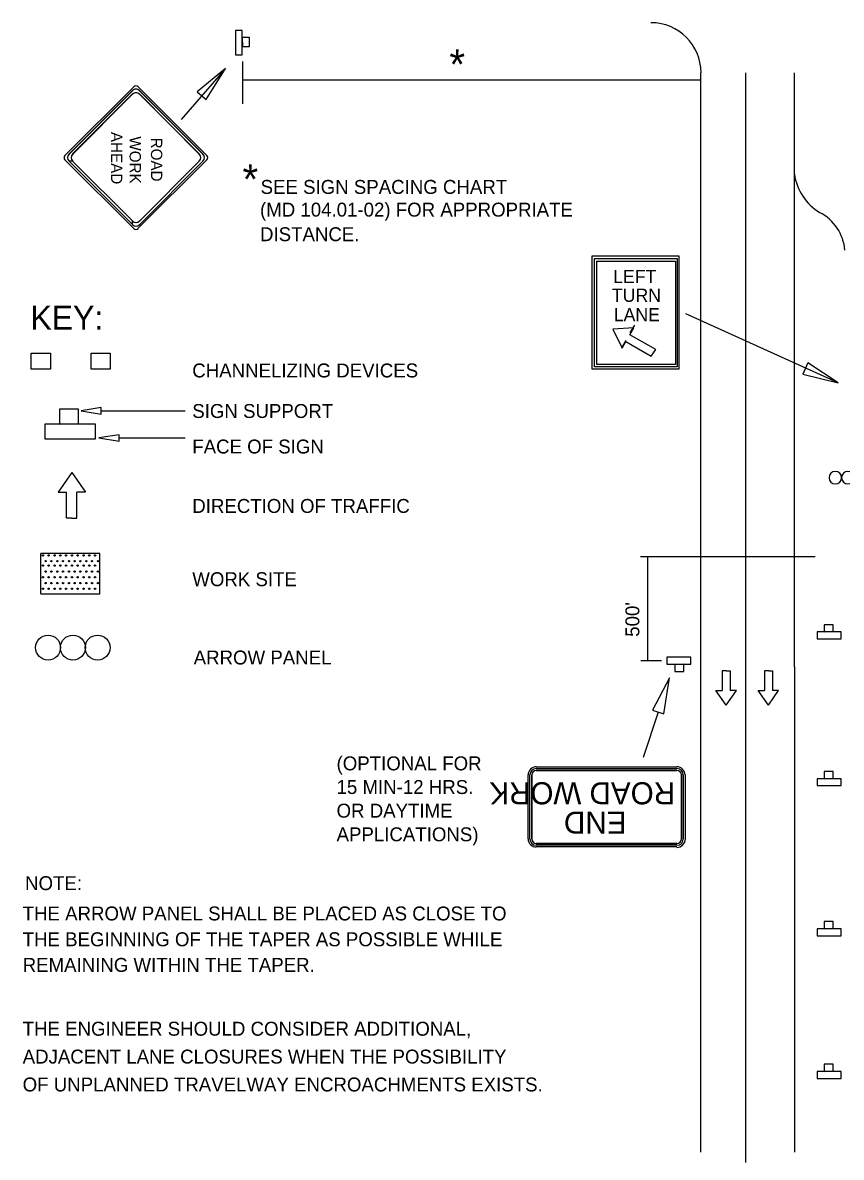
# Model space of a CAD drawing. Extents: x 1531.4 to 1538.6, y 1528.5 to 1539.8.
# Drawn here: x 1531.41 to 1534.932, y 1531.065 to 1535.949 of the extents above; entities that cross this region are included whole.
import ezdxf

# ---------------------------------------------------------------- set-up
doc = ezdxf.new("R2010")
doc.units = 0
for name, color, linetype in [('DETL-DIMS', 7, 'Continuous'), ('DETL-LINE', 7, 'Continuous'), ('DETL-NOTE', 7, 'Continuous'), ('DETL-TITL', 7, 'Continuous'), ('USER-BORD', 7, 'Continuous')]:
    doc.layers.add(name, color=color, linetype=linetype)

# ---------------------------------------------------------------- blocks, each defined once
blk = doc.blocks.new('PANEL')
at = {"layer": 'USER-BORD'}
for centre in [(0.00309, -0.00012), (0.00928, -0.00012), (0.01546, -0.00012)]:
    blk.add_circle(centre, 0.00312, dxfattribs=at)
blk = doc.blocks.new('DIR')
at = {"layer": 'USER-BORD'}
for p, q in [((0, 0.0001), (-0.0034, -0.0048)), ((0, 0.0001), (0.0034, -0.0048)), ((-0.0034, -0.0048), (-0.0013, -0.0048)), ((-0.0013, -0.0113), (-0.0013, -0.0048)), ((0.0034, -0.0048), (0.0013, -0.0048)), ((0.0013, -0.0113), (0.0013, -0.0048)), ((-0.0001, -0.0113), (-0.0013, -0.0113)), ((-0.0001, -0.0113), (0.0001, -0.0113)), ((0.0001, -0.0113), (0.0013, -0.0113))]:
    blk.add_line(p, q, dxfattribs=at)
blk = doc.blocks.new('SIGN')
at = {"layer": 'USER-BORD'}
for points in [[(-0.0013, 0.0018), (0.0011, 0.0019), (0.0011, 0.0037), (-0.0013, 0.0037)], [(-0.0031, 0.0018), (-0.0031, 0), (0.0032, 0), (0.0032, 0.0018)]]:
    blk.add_lwpolyline(points, close=True, dxfattribs=at)
blk = doc.blocks.new('R-BRD0')
at = {"layer": 'USER-BORD'}
for p, q in [((1.415, 2.996), (-1.412, 2.996)), ((-1.5, 2.909), (-1.5, 0.087)), ((-1.45, 0.2), (-1.45, 2.8)), ((-1.375, 2.725), (-1.375, 0.275)), ((-1.3, 2.95), (1.3, 2.95)), ((1.225, 2.875), (-1.225, 2.875)), ((1.375, 0.275), (1.375, 2.725)), ((1.45, 2.8), (1.45, 0.2)), ((1.502, 0.087), (1.502, 2.909)), ((-1.412, 0), (1.415, 0)), ((1.3, 0.05), (-1.3, 0.05)), ((-1.225, 0.125), (1.225, 0.125))]:
    blk.add_line(p, q, dxfattribs=at)
for centre, radius, start, end in [((-1.412, 2.909), 0.0875, 90, 180), ((1.415, 2.909), 0.0875, 0, 90), ((-1.3, 2.8), 0.15, 90, 180), ((-1.225, 2.725), 0.15, 90, 180), ((1.225, 2.725), 0.15, 0, 90), ((1.3, 2.8), 0.15, 0, 90), ((-1.412, 0.087), 0.0875, 180, 270), ((-1.3, 0.2), 0.15, 180, 270), ((-1.225, 0.275), 0.15, 180, 270), ((1.225, 0.275), 0.15, 270, 0), ((1.3, 0.2), 0.15, 270, 0), ((1.415, 0.087), 0.0875, 270, 0)]:
    blk.add_arc(centre, radius, start, end, dxfattribs=at)
blk = doc.blocks.new('W-BRD0')
at = {"layer": 'USER-BORD', "rotation": 45}
blk.add_blockref('R-BRD0', (1.0448, 1.0213), dxfattribs=at)

msp = doc.modelspace()

# ---------------------------------------------------------------- linework, layer by layer
at = {"layer": 'DETL-DIMS'}
for p, q in [((1532.2817, 1535.7516), (1532.091, 1535.5329)), ((1532.3557, 1535.7815), (1532.3557, 1535.5994)), ((1532.3557, 1535.7037), (1534.3286, 1535.7037)), ((1534.9193, 1534.3984), (1534.2634, 1534.6954)), ((1531.7474, 1534.278), (1532.1084, 1534.278)), ((1531.8241, 1534.1617), (1532.1084, 1534.1617)), ((1534.8199, 1533.6499), (1534.0683, 1533.6499)), ((1534.0977, 1533.6499), (1534.0977, 1533.2019)), ((1534.1579, 1533.2019), (1534.0692, 1533.2019)), ((1534.1441, 1532.9814), (1534.0804, 1532.7867))]:
    msp.add_line(p, q, dxfattribs=at)
for points in [[(1532.1605, 1535.6521), (1532.1987, 1535.6184), (1532.2817, 1535.7516)], [(1534.7879, 1534.4845), (1534.7668, 1534.4368), (1534.9193, 1534.3984)], [(1531.7474, 1534.2642), (1531.7474, 1534.2926), (1531.6613, 1534.278)], [(1531.8241, 1534.1471), (1531.8241, 1534.1755), (1531.7379, 1534.1617)], [(1534.12, 1532.99), (1534.1691, 1532.9736), (1534.1924, 1533.1287)]]:
    msp.add_lwpolyline(points, close=True, dxfattribs=at)
at = {"layer": 'DETL-LINE'}
for p, q in [((1534.3285, 1531.0873), (1534.3285, 1535.7337)), ((1534.7307, 1533.1768), (1534.7307, 1535.7337)), ((1531.8815, 1535.6563), (1531.609, 1535.3838)), ((1531.6247, 1535.3838), (1531.8815, 1535.6407)), ((1532.1854, 1535.3838), (1531.913, 1535.6563)), ((1531.913, 1535.6407), (1532.1697, 1535.3838)), ((1534.5198, 1535.6087), (1534.5198, 1531.0427)), ((1531.8815, 1535.0798), (1531.609, 1535.3523)), ((1531.609, 1535.3523), (1531.8815, 1535.0798)), ((1532.1697, 1535.3523), (1531.913, 1535.0955)), ((1531.913, 1535.0798), (1532.1854, 1535.3523)), ((1534.2351, 1534.9444), (1533.8585, 1534.9444)), ((1533.8585, 1534.9444), (1533.8585, 1534.4586)), ((1533.8696, 1534.9342), (1534.2253, 1534.9342)), ((1533.8696, 1534.4682), (1533.8696, 1534.9342)), ((1533.8807, 1534.923), (1534.2185, 1534.923)), ((1533.8807, 1534.4777), (1533.8807, 1534.923)), ((1534.2185, 1534.923), (1534.2185, 1534.4777)), ((1534.2253, 1534.9342), (1534.2253, 1534.4682)), ((1534.2351, 1534.4586), (1534.2351, 1534.9444)), ((1534.0419, 1534.6465), (1534.0228, 1534.6133)), ((1534.0044, 1534.5814), (1533.9858, 1534.5492)), ((1534.2185, 1534.4777), (1533.8807, 1534.4777)), ((1533.8585, 1534.4586), (1534.2351, 1534.4586)), ((1534.2253, 1534.4682), (1533.8696, 1534.4682)), ((1531.741, 1533.6648), (1531.487, 1533.6648)), ((1531.741, 1533.6648), (1531.487, 1533.6648)), ((1531.741, 1533.6648), (1531.487, 1533.6648)), ((1531.741, 1533.6648), (1531.487, 1533.6648)), ((1531.4871, 1533.4908), (1531.4871, 1533.6648)), ((1531.4871, 1533.4909), (1531.4871, 1533.6648)), ((1531.4956, 1533.6559), (1531.4956, 1533.6559)), ((1531.4964, 1533.6559), (1531.4964, 1533.6559)), ((1531.5212, 1533.6559), (1531.5212, 1533.6559)), ((1531.5212, 1533.6559), (1531.5212, 1533.6559)), ((1531.546, 1533.6559), (1531.546, 1533.6559)), ((1531.5468, 1533.6559), (1531.5468, 1533.6559)), ((1531.5708, 1533.6559), (1531.5708, 1533.6559)), ((1531.5716, 1533.6559), (1531.5716, 1533.6559)), ((1531.5956, 1533.6559), (1531.5956, 1533.6559)), ((1531.5964, 1533.6559), (1531.5964, 1533.6559)), ((1531.6212, 1533.6559), (1531.6212, 1533.6559)), ((1531.6212, 1533.6559), (1531.6212, 1533.6559)), ((1531.646, 1533.6559), (1531.646, 1533.6559)), ((1531.646, 1533.6559), (1531.646, 1533.6559)), ((1531.6708, 1533.6559), (1531.6708, 1533.6559)), ((1531.6716, 1533.6559), (1531.6716, 1533.6559)), ((1531.6956, 1533.6559), (1531.6956, 1533.6559)), ((1531.6964, 1533.6559), (1531.6964, 1533.6559)), ((1531.7212, 1533.6559), (1531.7212, 1533.6559)), ((1531.7212, 1533.6559), (1531.7212, 1533.6559)), ((1531.741, 1533.4908), (1531.741, 1533.6648)), ((1531.741, 1533.4908), (1531.741, 1533.6648)), ((1531.741, 1533.4908), (1531.741, 1533.6648)), ((1531.741, 1533.4908), (1531.741, 1533.6648)), ((1531.4956, 1533.6121), (1531.4956, 1533.6121)), ((1531.4964, 1533.6121), (1531.4964, 1533.6121)), ((1531.5084, 1533.6311), (1531.5084, 1533.6311)), ((1531.5084, 1533.6311), (1531.5084, 1533.6311)), ((1531.5212, 1533.6121), (1531.5212, 1533.6121)), ((1531.5212, 1533.6121), (1531.5212, 1533.6121)), ((1531.5332, 1533.6311), (1531.5332, 1533.6311)), ((1531.5332, 1533.6311), (1531.5332, 1533.6311)), ((1531.546, 1533.6121), (1531.546, 1533.6121)), ((1531.5468, 1533.6121), (1531.5468, 1533.6121)), ((1531.5588, 1533.6311), (1531.5588, 1533.6311)), ((1531.5588, 1533.6311), (1531.5588, 1533.6311)), ((1531.5708, 1533.6121), (1531.5708, 1533.6121)), ((1531.5716, 1533.6121), (1531.5716, 1533.6121)), ((1531.5836, 1533.6311), (1531.5836, 1533.6311)), ((1531.5836, 1533.6311), (1531.5836, 1533.6311)), ((1531.5956, 1533.6121), (1531.5956, 1533.6121)), ((1531.5964, 1533.6121), (1531.5964, 1533.6121)), ((1531.6084, 1533.6311), (1531.6084, 1533.6311)), ((1531.6084, 1533.6311), (1531.6084, 1533.6311)), ((1531.6212, 1533.6121), (1531.6212, 1533.6121)), ((1531.6212, 1533.6121), (1531.6212, 1533.6121)), ((1531.6332, 1533.6311), (1531.6332, 1533.6311)), ((1531.6332, 1533.6311), (1531.6332, 1533.6311)), ((1531.646, 1533.6121), (1531.646, 1533.6121)), ((1531.646, 1533.6121), (1531.646, 1533.6121)), ((1531.658, 1533.6311), (1531.658, 1533.6311)), ((1531.658, 1533.6311), (1531.658, 1533.6311)), ((1531.6708, 1533.6121), (1531.6708, 1533.6121)), ((1531.6716, 1533.6121), (1531.6716, 1533.6121)), ((1531.6836, 1533.6311), (1531.6836, 1533.6311)), ((1531.6836, 1533.6311), (1531.6836, 1533.6311)), ((1531.6956, 1533.6121), (1531.6956, 1533.6121)), ((1531.6964, 1533.6121), (1531.6964, 1533.6121)), ((1531.7084, 1533.6311), (1531.7084, 1533.6311)), ((1531.7084, 1533.6311), (1531.7084, 1533.6311)), ((1531.7212, 1533.6121), (1531.7212, 1533.6121)), ((1531.7212, 1533.6121), (1531.7212, 1533.6121)), ((1531.7332, 1533.6311), (1531.7332, 1533.6311)), ((1531.7332, 1533.6311), (1531.7332, 1533.6311)), ((1531.4956, 1533.5617), (1531.4956, 1533.5617)), ((1531.4964, 1533.5617), (1531.4964, 1533.5617)), ((1531.5084, 1533.5865), (1531.5084, 1533.5865)), ((1531.5212, 1533.5617), (1531.5212, 1533.5617)), ((1531.5212, 1533.5617), (1531.5212, 1533.5617)), ((1531.5332, 1533.5865), (1531.5332, 1533.5865)), ((1531.546, 1533.5617), (1531.546, 1533.5617)), ((1531.5468, 1533.5617), (1531.5468, 1533.5617)), ((1531.5588, 1533.5865), (1531.5588, 1533.5865)), ((1531.5708, 1533.5617), (1531.5708, 1533.5617)), ((1531.5716, 1533.5617), (1531.5716, 1533.5617)), ((1531.5836, 1533.5865), (1531.5836, 1533.5865)), ((1531.5956, 1533.5617), (1531.5956, 1533.5617)), ((1531.5964, 1533.5617), (1531.5964, 1533.5617)), ((1531.6084, 1533.5865), (1531.6084, 1533.5865)), ((1531.6212, 1533.5617), (1531.6212, 1533.5617)), ((1531.6212, 1533.5617), (1531.6212, 1533.5617)), ((1531.6332, 1533.5865), (1531.6332, 1533.5865)), ((1531.646, 1533.5617), (1531.646, 1533.5617)), ((1531.646, 1533.5617), (1531.646, 1533.5617)), ((1531.658, 1533.5865), (1531.658, 1533.5865)), ((1531.6708, 1533.5617), (1531.6708, 1533.5617)), ((1531.6716, 1533.5617), (1531.6716, 1533.5617)), ((1531.6836, 1533.5865), (1531.6836, 1533.5865)), ((1531.6956, 1533.5617), (1531.6956, 1533.5617)), ((1531.6964, 1533.5617), (1531.6964, 1533.5617)), ((1531.7084, 1533.5865), (1531.7084, 1533.5865)), ((1531.7212, 1533.5617), (1531.7212, 1533.5617)), ((1531.7212, 1533.5617), (1531.7212, 1533.5617)), ((1531.7332, 1533.5865), (1531.7332, 1533.5865)), ((1531.4956, 1533.5125), (1531.4956, 1533.5125)), ((1531.4964, 1533.5125), (1531.4964, 1533.5125)), ((1531.5084, 1533.5369), (1531.5084, 1533.5369)), ((1531.5084, 1533.5369), (1531.5084, 1533.5369)), ((1531.5212, 1533.5125), (1531.5212, 1533.5125)), ((1531.5212, 1533.5125), (1531.5212, 1533.5125)), ((1531.5332, 1533.5369), (1531.5332, 1533.5369)), ((1531.5332, 1533.5369), (1531.5332, 1533.5369)), ((1531.546, 1533.5125), (1531.546, 1533.5125)), ((1531.5468, 1533.5125), (1531.5468, 1533.5125)), ((1531.5588, 1533.5369), (1531.5588, 1533.5369)), ((1531.5588, 1533.5369), (1531.5588, 1533.5369)), ((1531.5708, 1533.5125), (1531.5708, 1533.5125)), ((1531.5716, 1533.5125), (1531.5716, 1533.5125)), ((1531.5836, 1533.5369), (1531.5836, 1533.5369)), ((1531.5836, 1533.5369), (1531.5836, 1533.5369)), ((1531.5956, 1533.5125), (1531.5956, 1533.5125)), ((1531.5964, 1533.5125), (1531.5964, 1533.5125)), ((1531.6084, 1533.5369), (1531.6084, 1533.5369)), ((1531.6084, 1533.5369), (1531.6084, 1533.5369)), ((1531.6212, 1533.5125), (1531.6212, 1533.5125)), ((1531.6212, 1533.5125), (1531.6212, 1533.5125)), ((1531.6332, 1533.5369), (1531.6332, 1533.5369)), ((1531.6332, 1533.5369), (1531.6332, 1533.5369)), ((1531.646, 1533.5125), (1531.646, 1533.5125)), ((1531.646, 1533.5125), (1531.646, 1533.5125)), ((1531.658, 1533.5369), (1531.658, 1533.5369)), ((1531.658, 1533.5369), (1531.658, 1533.5369)), ((1531.6708, 1533.5125), (1531.6708, 1533.5125)), ((1531.6716, 1533.5125), (1531.6716, 1533.5125)), ((1531.6836, 1533.5369), (1531.6836, 1533.5369)), ((1531.6836, 1533.5369), (1531.6836, 1533.5369)), ((1531.6956, 1533.5125), (1531.6956, 1533.5125)), ((1531.6964, 1533.5125), (1531.6964, 1533.5125)), ((1531.7084, 1533.5369), (1531.7084, 1533.5369)), ((1531.7084, 1533.5369), (1531.7084, 1533.5369)), ((1531.7212, 1533.5125), (1531.7212, 1533.5125)), ((1531.7212, 1533.5125), (1531.7212, 1533.5125)), ((1531.7332, 1533.5369), (1531.7332, 1533.5369)), ((1531.7332, 1533.5369), (1531.7332, 1533.5369)), ((1531.4871, 1533.4908), (1531.7411, 1533.4908)), ((1534.7307, 1533.1768), (1534.7307, 1531.0873)), ((1533.5848, 1532.4358), (1533.5848, 1532.7108)), ((1533.5923, 1532.4358), (1533.5923, 1532.7108)), ((1533.5923, 1532.4358), (1533.5923, 1532.7108)), ((1533.6003, 1532.7108), (1533.6003, 1532.4358)), ((1533.6003, 1532.4358), (1533.6003, 1532.7108)), ((1533.6199, 1532.746), (1534.2249, 1532.746)), ((1533.6199, 1532.7384), (1533.6199, 1532.7383)), ((1533.6199, 1532.7383), (1534.2249, 1532.7383)), ((1533.6199, 1532.7383), (1534.2249, 1532.7383)), ((1533.6199, 1532.7306), (1533.6199, 1532.7304)), ((1534.2249, 1532.7304), (1533.6199, 1532.7304)), ((1533.6199, 1532.7304), (1534.2249, 1532.7304)), ((1534.2448, 1532.4358), (1534.2448, 1532.7108)), ((1534.2448, 1532.7108), (1534.2448, 1532.4358)), ((1534.2521, 1532.7108), (1534.2521, 1532.4358)), ((1534.2522, 1532.7108), (1534.2521, 1532.7108)), ((1534.2521, 1532.7108), (1534.2521, 1532.4358)), ((1534.2603, 1532.7108), (1534.2603, 1532.4358)), ((1533.6199, 1532.4158), (1534.2249, 1532.4158)), ((1534.2249, 1532.4158), (1533.6199, 1532.4158)), ((1534.2249, 1532.4086), (1533.6199, 1532.4086)), ((1534.2249, 1532.4086), (1533.6199, 1532.4086)), ((1534.2249, 1532.4009), (1533.6199, 1532.4009))]:
    msp.add_line(p, q, dxfattribs=at)
for points in [[(1534.5198, 1535.7337), (1534.5198, 1535.4837)], [(1531.6247, 1535.3523), (1531.609, 1535.3523), (1531.8815, 1535.0798), (1531.8815, 1535.0955)], [(1534.5198, 1534.7337), (1534.5198, 1534.6087)], [(1534.5198, 1534.6087), (1534.5198, 1534.4837)], [(1534.5198, 1533.7337), (1534.5198, 1533.6087)], [(1534.5198, 1533.6087), (1534.5198, 1533.4837)], [(1534.5198, 1532.7337), (1534.5198, 1532.6087)], [(1534.5198, 1532.6087), (1534.5198, 1532.4837)], [(1534.5198, 1531.7337), (1534.5198, 1531.6087)], [(1534.5198, 1531.6087), (1534.5198, 1531.4837)]]:
    msp.add_lwpolyline(points, dxfattribs=at)
for points in [[(1534.0392, 1534.6357), (1533.9485, 1534.6302), (1533.9888, 1534.5481), (1534.0054, 1534.577), (1534.1147, 1534.5142), (1534.1338, 1534.5426), (1534.022, 1534.6058)], [(1531.4468, 1534.4573), (1531.4468, 1534.527), (1531.5295, 1534.527), (1531.5295, 1534.4573)], [(1531.7036, 1534.4573), (1531.7036, 1534.527), (1531.7862, 1534.527), (1531.7862, 1534.4573)]]:
    msp.add_lwpolyline(points, close=True, dxfattribs=at)
for centre in [(1531.4964, 1533.6559), (1531.5212, 1533.6559), (1531.5468, 1533.6559), (1531.5716, 1533.6559), (1531.5964, 1533.6559), (1531.6212, 1533.6559), (1531.646, 1533.6559), (1531.6716, 1533.6559), (1531.6964, 1533.6559), (1531.7212, 1533.6559), (1531.4964, 1533.6121), (1531.5084, 1533.6311), (1531.5084, 1533.5865), (1531.5212, 1533.6121), (1531.5332, 1533.6311), (1531.5332, 1533.5865), (1531.5468, 1533.6121), (1531.5588, 1533.6311), (1531.5588, 1533.5865), (1531.5716, 1533.6121), (1531.5836, 1533.6311), (1531.5836, 1533.5865), (1531.5964, 1533.6121), (1531.6084, 1533.6311), (1531.6084, 1533.5865), (1531.6212, 1533.6121), (1531.6332, 1533.6311), (1531.6332, 1533.5865), (1531.646, 1533.6121), (1531.658, 1533.6311), (1531.658, 1533.5865), (1531.6716, 1533.6121), (1531.6836, 1533.6311), (1531.6836, 1533.5865), (1531.6964, 1533.6121), (1531.7084, 1533.6311), (1531.7084, 1533.5865), (1531.7212, 1533.6121), (1531.7332, 1533.6311), (1531.7332, 1533.5865), (1531.4964, 1533.5617), (1531.5212, 1533.5617), (1531.5468, 1533.5617), (1531.5716, 1533.5617), (1531.5964, 1533.5617), (1531.6212, 1533.5617), (1531.646, 1533.5617), (1531.6716, 1533.5617), (1531.6964, 1533.5617), (1531.7212, 1533.5617), (1531.4964, 1533.5125), (1531.5084, 1533.5369), (1531.5212, 1533.5125), (1531.5332, 1533.5369), (1531.5468, 1533.5125), (1531.5588, 1533.5369), (1531.5716, 1533.5125), (1531.5836, 1533.5369), (1531.5964, 1533.5125), (1531.6084, 1533.5369), (1531.6212, 1533.5125), (1531.6332, 1533.5369), (1531.646, 1533.5125), (1531.658, 1533.5369), (1531.6716, 1533.5125), (1531.6836, 1533.5369), (1531.6964, 1533.5125), (1531.7084, 1533.5369), (1531.7212, 1533.5125), (1531.7332, 1533.5369)]:
    msp.add_circle(centre, 0.00291, dxfattribs=at)
for centre, radius, start, end in [((1534.1132, 1535.7337), 0.2154, 0, 90), ((1534.9614, 1535.3305), 0.2331, 188.3753, 238.2504), ((1534.7476, 1534.9534), 0.2007, 4.57, 63.0108), ((1533.6199, 1532.7108), 0.0351, 90, 180), ((1533.6199, 1532.7108), 0.0275, 90, 180), ((1533.6199, 1532.7108), 0.0275, 90, 180), ((1533.6199, 1532.7108), 0.0197, 90, 180), ((1533.6199, 1532.7108), 0.0197, 90, 180), ((1534.2247, 1532.7108), 0.0351, 0, 90), ((1534.2247, 1532.7108), 0.0275, 0, 90), ((1534.2247, 1532.7108), 0.0275, 0, 90), ((1534.2247, 1532.7108), 0.0197, 0, 90), ((1534.2247, 1532.7108), 0.0197, 0, 90), ((1533.6199, 1532.4359), 0.0351, 180, 270), ((1533.6199, 1532.4359), 0.0275, 180, 270), ((1533.6199, 1532.4359), 0.0275, 180, 270), ((1533.6199, 1532.4359), 0.0197, 180, 270), ((1533.6199, 1532.4359), 0.0197, 180, 270), ((1534.2247, 1532.4359), 0.0197, 270, 0), ((1534.2247, 1532.4359), 0.0275, 270, 0), ((1534.2247, 1532.4359), 0.0368, 270, 0), ((1534.2247, 1532.4359), 0.0275, 270, 0), ((1534.2247, 1532.4359), 0.0197, 270, 0)]:
    msp.add_arc(centre, radius, start, end, dxfattribs=at)
for centre, start_param, end_param in [((1531.8971, 1535.6407), 2.356194, 3.926991), ((1531.8971, 1535.625), 2.356194, 3.926991), ((1531.6246, 1535.3681), 3.926991, 5.497787), ((1531.6404, 1535.3681), 3.926991, 5.497787), ((1532.1539, 1535.3681), 0.785398, 2.356194), ((1532.1696, 1535.3681), 0.785398, 2.356194), ((1531.8972, 1535.1113), 5.497787, 7.068583), ((1531.8971, 1535.0955), 5.497787, 7.068583)]:
    msp.add_ellipse(centre, major_axis=(0, -0.0222), ratio=0.99974, start_param=start_param, end_param=end_param, dxfattribs=at)

# ---------------------------------------------------------------- block references
for name, p, xscale, yscale, rotation in [('SIGN', (1532.3249, 1535.8641), 16.482020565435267, 16.482020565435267, -90.00000000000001), ('W-BRD0', (1531.8948, 1535.6768), 0.14822291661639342, 0.14826149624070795, 180), ('PANEL', (1535.0401, 1533.9916), 8.61495264, -8.61495264, 180), ('SIGN', (1534.2337, 1533.2174), 16.482020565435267, 16.482020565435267, 180), ('DIR', (1534.437, 1533.0129), 12.922428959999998, 12.922428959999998, 180), ('DIR', (1534.6188, 1533.0129), 12.922428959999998, 12.922428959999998, 180)]:
    msp.add_blockref(name, p, dxfattribs=dict(at, xscale=xscale, yscale=yscale, rotation=rotation))
for name, p, xscale, yscale in [('SIGN', (1531.6122, 1534.1582), 34.45981056, 34.45981056), ('DIR', (1531.6208, 1534.011), 17.22990528, 17.22990528), ('SIGN', (1534.8795, 1533.2966), 16.482020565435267, 16.482020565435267), ('PANEL', (1531.4657, 1533.2612), 17.22990528, 17.22990528), ('SIGN', (1534.8795, 1532.6652), 16.482020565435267, 16.482020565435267), ('SIGN', (1534.8795, 1532.0184), 16.482020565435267, 16.482020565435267), ('SIGN', (1534.8795, 1531.4045), 16.482020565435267, 16.482020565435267)]:
    msp.add_blockref(name, p, dxfattribs=dict(at, xscale=xscale, yscale=yscale))

# ---------------------------------------------------------------- texts
for s, height, rotation, p in [('AHEAD', 0.04891, 270, (1531.7895, 1535.4789)), ('WORK', 0.04891, 270, (1531.8695, 1535.4596)), ('ROAD ', 0.04891, 270, (1531.9615, 1535.4542)), ('ROAD WORK', 0.09521, 180, (1534.2168, 1532.6797)), ('END', 0.09521, 180, (1534.0075, 1532.5531))]:
    msp.add_text(s, height=height, rotation=rotation, dxfattribs=at).set_placement(p)
for s, p in [('LEFT', (1533.9505, 1534.8282)), ('TURN', (1533.9452, 1534.7472)), ('LANE', (1533.9531, 1534.6637))]:
    msp.add_text(s, height=0.05686, dxfattribs=at).set_placement(p)
at = {"layer": 'DETL-NOTE'}
for s, height, p in [('*', 0.1292, (1533.2459, 1535.7055)), ('*', 0.1292, (1532.3556, 1535.2108)), ('SEE SIGN SPACING CHART ', 0.06, (1532.4334, 1535.2121)), ('(MD 104.01-02) FOR APPROPRIATE ', 0.06, (1532.4309, 1535.1143)), ('DISTANCE. ', 0.06, (1532.4309, 1535.0085)), ('CHANNELIZING DEVICES', 0.06, (1532.1394, 1534.422)), ('SIGN SUPPORT', 0.06, (1532.1394, 1534.2475)), ('FACE OF SIGN', 0.06, (1532.1394, 1534.0946)), ('DIRECTION OF TRAFFIC', 0.06, (1532.1394, 1533.8388)), ('WORK SITE', 0.06, (1532.1394, 1533.5235)), ('ARROW PANEL', 0.06, (1532.1455, 1533.1864)), ('(OPTIONAL FOR', 0.06, (1532.7603, 1532.7307)), ('15 MIN-12 HRS. ', 0.06, (1532.7603, 1532.6289)), ('OR DAYTIME', 0.06, (1532.7603, 1532.5271)), ('APPLICATIONS)', 0.06, (1532.7603, 1532.4253)), ('NOTE:', 0.06, (1531.4199, 1532.2151)), ('THE ARROW PANEL SHALL BE PLACED AS CLOSE TO', 0.06, (1531.4095, 1532.0846)), ('THE BEGINNING OF THE TAPER AS POSSIBLE WHILE', 0.06, (1531.4095, 1531.9735)), ('REMAINING WITHIN THE TAPER.', 0.06, (1531.4095, 1531.8632)), ('THE ENGINEER SHOULD CONSIDER ADDITIONAL,', 0.06, (1531.4095, 1531.5885)), ('ADJACENT LANE CLOSURES WHEN THE POSSIBILITY', 0.06, (1531.4095, 1531.4685)), ('OF UNPLANNED TRAVELWAY ENCROACHMENTS EXISTS.', 0.06, (1531.4095, 1531.3485))]:
    msp.add_text(s, height=height, dxfattribs=at).set_placement(p)
msp.add_text("500'", height=0.06, rotation=90, dxfattribs=at).set_placement((1534.0632, 1533.3057))
at = {"layer": 'DETL-TITL'}
msp.add_text('KEY:', height=0.1026, dxfattribs=at).set_placement((1531.4433, 1534.6277))

doc.saveas('drawing.dxf')
